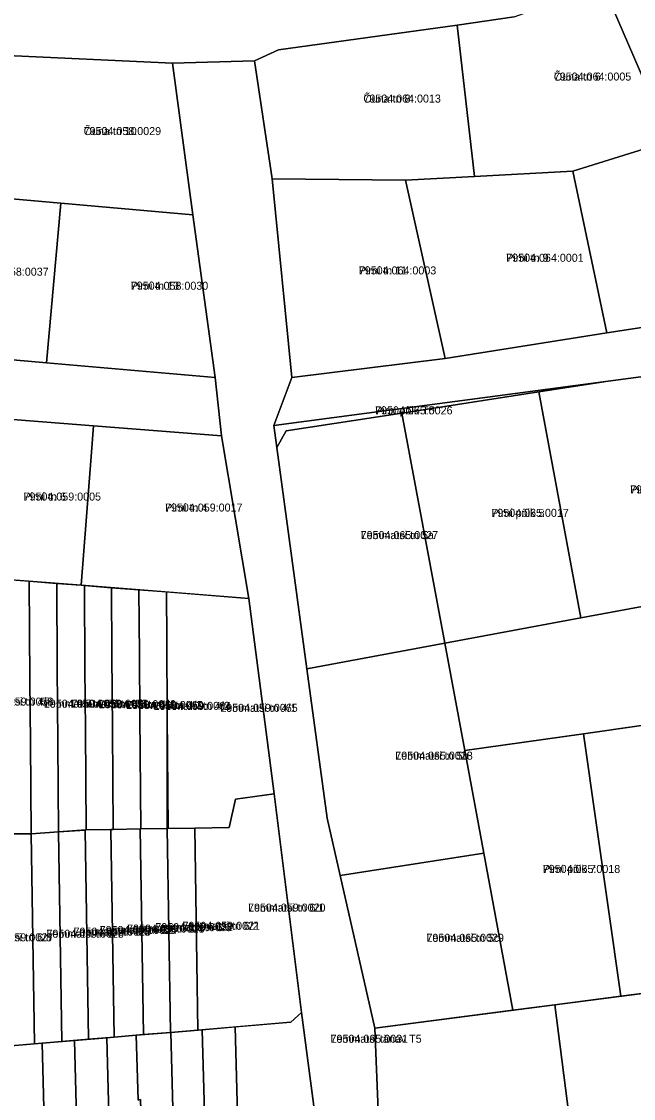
# Model space of a CAD drawing. Extents: x 643847 to 663718, y 6468443 to 6482775.
# Drawn here: x 657992.5 to 658107, y 6471569.9 to 6471771.7 of the extents above; entities that cross this region are included whole.
import ezdxf

# ---------------------------------------------------------------- set-up
doc = ezdxf.new("R2010")
doc.units = 0
for name, color, linetype in [('L_AADRESS', 7, 'Continuous'), ('PIIR', 7, 'Continuous'), ('TUNNUS', 7, 'Continuous')]:
    doc.layers.add(name, color=color, linetype=linetype)

msp = doc.modelspace()

# ---------------------------------------------------------------- linework, layer by layer
at = {"layer": 'PIIR'}
for points in [[(658130.86, 6471790.16), (658143.53, 6471759.24), (658139.36, 6471757.85), (658118.69, 6471750.96), (658113.89, 6471749.36), (658101.3, 6471778.58)], [(658084.71, 6471772.59), (658101.3, 6471778.58), (658113.89, 6471749.36), (658095.69, 6471743.62), (658077.27, 6471742.66), (658074.05, 6471771.01)], [(658040.59, 6471766.41), (658074.05, 6471771.01), (658077.27, 6471742.66), (658064.37, 6471741.98), (658039.4, 6471742.24), (658036.05, 6471764.29)], [(658020.75, 6471763.87), (658024.55, 6471735.47), (657999.78, 6471737.65), (657983.51, 6471739.07), (657988.38, 6471765.35)], [(658102.07, 6471713.38), (658095.69, 6471743.62), (658113.89, 6471749.36), (658118.69, 6471750.96), (658128.58, 6471717.44)], [(658240.59, 6471748.79), (658243.87, 6471740.33), (658192.37, 6471722.19), (658170.1, 6471714.25), (658165.76, 6471712.72), (658143.94, 6471709.85), (658115.89, 6471706.11), (658102.29, 6471704.3), (658039.68, 6471696.01), (658043.07, 6471704.97), (658071.81, 6471708.56), (658102.07, 6471713.38), (658128.58, 6471717.44), (658152.4, 6471721.29), (658165.18, 6471723.35), (658173.83, 6471725.83), (658194.24, 6471732.34)], [(658071.81, 6471708.56), (658064.37, 6471741.98), (658077.27, 6471742.66), (658095.69, 6471743.62), (658102.07, 6471713.38)], [(658043.07, 6471704.97), (658039.4, 6471742.24), (658064.37, 6471741.98), (658071.81, 6471708.56)], [(657966.25, 6471710.48), (657968.91, 6471740.35), (657983.51, 6471739.07), (657999.78, 6471737.65), (657997.15, 6471707.76)], [(658028.68, 6471704.99), (657997.15, 6471707.76), (657999.78, 6471737.65), (658024.55, 6471735.47)], [(658028.68, 6471704.99), (658029.88, 6471694.09), (658005.95, 6471695.96), (657982.03, 6471697.81), (657958.1, 6471699.66), (657934.19, 6471701.58), (657908.89, 6471703.62), (657886.93, 6471704.97), (657856.07, 6471706.87), (657856.98, 6471720.08), (657909.44, 6471715.48), (657934.36, 6471713.29), (657966.25, 6471710.48), (657997.15, 6471707.76)], [(658115.89, 6471706.11), (658123.55, 6471664.85), (658097.18, 6471659.96), (658089.32, 6471702.3), (658102.29, 6471704.3)], [(658102.29, 6471704.3), (658089.32, 6471702.3), (658063.69, 6471698.33), (658042.02, 6471694.97), (658040.24, 6471691.85), (658039.68, 6471696.01)], [(658089.32, 6471702.3), (658097.18, 6471659.96), (658071.69, 6471655.22), (658063.69, 6471698.33)], [(658005.95, 6471695.96), (658005.56, 6471690.97), (658003.62, 6471666.05), (657979.71, 6471667.91), (657981.64, 6471692.83), (657982.03, 6471697.81)], [(658063.69, 6471698.33), (658071.69, 6471655.22), (658045.88, 6471650.42), (658040.24, 6471691.85), (658042.02, 6471694.97)], [(658029.88, 6471694.09), (658035.03, 6471663.61), (658003.62, 6471666.05), (658005.56, 6471690.97), (658005.95, 6471695.96)], [(657993.88, 6471666.81), (657994.02, 6471648.2), (657994.1, 6471636.63), (657994.24, 6471619.48), (657989.23, 6471619.48), (657977.44, 6471619.45), (657975.43, 6471651.95), (657973.59, 6471652.12), (657975.1, 6471668.27), (657979.71, 6471667.91), (657988.87, 6471667.19)], [(657993.88, 6471666.81), (657999.03, 6471666.41), (657999.15, 6471650.58), (657999.26, 6471636.63), (657999.38, 6471619.88), (657994.24, 6471619.48), (657994.1, 6471636.63), (657994.02, 6471648.2)], [(657999.03, 6471666.41), (658003.62, 6471666.05), (658004.21, 6471666), (658004.33, 6471650.51), (658004.41, 6471639.05), (658004.55, 6471620.22), (657999.38, 6471619.88), (657999.26, 6471636.63), (657999.15, 6471650.58)], [(658004.21, 6471666), (658009.28, 6471665.61), (658009.37, 6471653.06), (658009.49, 6471639.06), (658009.62, 6471620.32), (658009.19, 6471620.31), (658004.55, 6471620.22), (658004.41, 6471639.05), (658004.33, 6471650.51)], [(658009.28, 6471665.61), (658014.44, 6471665.21), (658014.53, 6471653.09), (658014.62, 6471641.57), (658014.77, 6471620.41), (658014.65, 6471620.4), (658009.62, 6471620.32), (658009.49, 6471639.06), (658009.37, 6471653.06)], [(658019.57, 6471664.81), (658019.63, 6471655.68), (658019.74, 6471641.64), (658019.91, 6471620.49), (658019.72, 6471620.49), (658014.77, 6471620.41), (658014.62, 6471641.57), (658014.53, 6471653.09), (658014.44, 6471665.21)], [(658035.03, 6471663.61), (658039.75, 6471626.99), (658032.54, 6471626.01), (658031.36, 6471620.7), (658024.88, 6471620.58), (658019.72, 6471620.49), (658019.74, 6471641.64), (658019.63, 6471655.68), (658019.57, 6471664.81)], [(658071.69, 6471655.22), (658075.44, 6471635.08), (658079, 6471615.86), (658052.09, 6471611.67), (658049.69, 6471622.45), (658045.88, 6471650.42)], [(658119.87, 6471641.41), (658126.07, 6471591.82), (658104.69, 6471589.05), (658097.7, 6471638.25)], [(658097.7, 6471638.25), (658104.69, 6471589.05), (658092.3, 6471587.44), (658084.47, 6471586.43), (658079, 6471615.86), (658075.44, 6471635.08)], [(658031.36, 6471620.7), (658032.54, 6471626.01), (658039.75, 6471626.99), (658044.85, 6471585.99), (658042.89, 6471584.19), (658025.47, 6471582.73), (658024.88, 6471620.58)], [(658019.72, 6471620.49), (658020.34, 6471582.3), (658015.26, 6471581.87), (658014.65, 6471620.4), (658014.77, 6471620.41)], [(658024.88, 6471620.58), (658025.47, 6471582.73), (658020.34, 6471582.3), (658019.72, 6471620.49)], [(657977.44, 6471619.45), (657994.24, 6471619.48), (657994.85, 6471580.16), (657983, 6471579.16), (657980.44, 6471581.49), (657973.64, 6471595.24), (657972.88, 6471619.22)], [(657999.38, 6471619.88), (657999.99, 6471580.59), (657994.85, 6471580.16), (657994.24, 6471619.48)], [(658004.37, 6471620.21), (658004.99, 6471581), (657999.99, 6471580.59), (657999.38, 6471619.88)], [(658009.19, 6471620.31), (658009.82, 6471581.42), (658004.99, 6471581), (658004.37, 6471620.21), (658004.55, 6471620.22)], [(658014.65, 6471620.4), (658015.26, 6471581.87), (658009.82, 6471581.42), (658009.19, 6471620.31), (658009.62, 6471620.32)], [(658079, 6471615.86), (658084.47, 6471586.43), (658058.59, 6471583.07), (658052.09, 6471611.67)], [(658096.63, 6471553.82), (658092.3, 6471587.44), (658126.07, 6471591.82), (658130.25, 6471558.12)], [(658060, 6471549.15), (658058.59, 6471583.07), (658092.3, 6471587.44), (658096.63, 6471553.82)], [(658049.93, 6471547.63), (658033.46, 6471545.74), (658032.45, 6471583.31), (658042.89, 6471584.19), (658044.85, 6471585.99)], [(658021.43, 6471544.36), (658015.79, 6471543.72), (658015.23, 6471563.86), (658014.89, 6471563.86), (658014.74, 6471569.7), (658014.31, 6471569.62), (658013.93, 6471581.76), (658020.41, 6471582.3)], [(658027.32, 6471545.04), (658021.43, 6471544.36), (658020.41, 6471582.3), (658026.3, 6471582.8)], [(658033.46, 6471545.74), (658027.32, 6471545.04), (658026.3, 6471582.8), (658032.45, 6471583.31)], [(657997.29, 6471541.6), (657991.02, 6471540.88), (657983, 6471579.16), (657996.33, 6471580.28)], [(658003.34, 6471542.29), (657997.29, 6471541.6), (657996.33, 6471580.28), (658002.38, 6471580.79)], [(658009.39, 6471542.98), (658003.34, 6471542.29), (658002.38, 6471580.79), (658008.44, 6471581.3)], [(658014.31, 6471569.62), (658014.74, 6471569.7), (658014.89, 6471563.86), (658015.23, 6471563.86), (658015.79, 6471543.72), (658009.39, 6471542.98), (658008.44, 6471581.3), (658013.93, 6471581.76)]]:
    msp.add_lwpolyline(points, close=True, dxfattribs=at)
for points in [[(658084.71, 6471772.59), (658074.05, 6471771.01), (658040.59, 6471766.41), (658036.05, 6471764.29), (658020.75, 6471763.87), (657988.38, 6471765.35), (657966.11, 6471776.41)], [(658049.93, 6471547.63), (658044.85, 6471585.99), (658039.75, 6471626.99), (658035.03, 6471663.61), (658029.88, 6471694.09), (658028.68, 6471704.99), (658024.55, 6471735.47), (658020.75, 6471763.87), (658036.05, 6471764.29), (658039.4, 6471742.24), (658043.07, 6471704.97), (658039.68, 6471696.01), (658040.24, 6471691.85), (658045.88, 6471650.42), (658049.69, 6471622.45), (658052.09, 6471611.67), (658058.59, 6471583.07), (658060, 6471549.15)], [(658119.87, 6471641.41), (658097.7, 6471638.25), (658075.44, 6471635.08), (658071.69, 6471655.22), (658097.18, 6471659.96), (658123.55, 6471664.85)]]:
    msp.add_lwpolyline(points, dxfattribs=at)

# ---------------------------------------------------------------- texts
at = {"layer": 'L_AADRESS'}
for s, p in [('Õuna tn 6', (658092.13, 6471760.62)), ('Õuna tn 8', (658056.47, 6471756.5)), ('Õuna tn 10', (658004.08, 6471750.41)), ('Pirni tn 9', (658083.22, 6471726.67)), ('Pirni tn 11', (658055.61, 6471724.3)), ('Pirni tn 13', (658012.91, 6471721.43)), ('Pirni põik T5', (658058.66, 6471698.08)), ('Pirni tn 6', (657992.83, 6471681.93)), ('Pirni põik 3', (658106.43, 6471683.26)), ('Pirni tn 4', (658019.32, 6471679.87)), ('Pirni põik 5', (658080.43, 6471678.88)), ('Lemmatsi tn 5a', (658055.96, 6471674.71)), ('Lemmatsi tn 4/7', (657983.92, 6471643.52)), ('Lemmatsi tn 4/6', (657996.63, 6471643.13)), ('Lemmatsi tn 4/5', (658001.79, 6471643.12)), ('Lemmatsi tn 4/4', (658006.91, 6471643.03)), ('Lemmatsi tn 4/3', (658012.03, 6471642.88)), ('Lemmatsi tn 4/2', (658017.17, 6471642.72)), ('Lemmatsi tn 4/1', (658029.66, 6471642.35)), ('Lemmatsi tn 5b', (658062.44, 6471633.39)), ('Pirni põik 7', (658090.06, 6471612.16)), ('Lemmatsi tn 6/1', (658034.87, 6471604.92)), ('Lemmatsi tn 6/5', (658007.09, 6471600.73)), ('Lemmatsi tn 6/4', (658012.22, 6471600.99)), ('Lemmatsi tn 6/3', (658017.5, 6471601.26)), ('Lemmatsi tn 6/2', (658022.59, 6471601.51)), ('Lemmatsi tn 6/8', (657983.87, 6471599.35)), ('Lemmatsi tn 6/7', (657997.12, 6471600.03)), ('Lemmatsi tn 6/6', (658002.19, 6471600.42)), ('Lemmatsi tn 5c', (658068.28, 6471599.26)), ('Lemmatsi tänav T5', (658050.32, 6471580.35))]:
    msp.add_text(s, height=1.5, dxfattribs=at).set_placement(p)
at = {"layer": 'TUNNUS'}
for s, p in [('79504:064:0005', (658092.13, 6471760.62)), ('79504:064:0013', (658056.47, 6471756.5)), ('79504:058:0029', (658004.08, 6471750.41)), ('79504:064:0001', (658083.22, 6471726.67)), ('79504:058:0037', (657983.02, 6471724.06)), ('79504:064:0003', (658055.61, 6471724.3)), ('79504:058:0030', (658012.91, 6471721.43)), ('79504:065:0026', (658058.66, 6471698.08)), ('79504:059:0005', (657992.83, 6471681.93)), ('79504:065:0016', (658106.43, 6471683.26)), ('79504:059:0017', (658019.32, 6471679.87)), ('79504:065:0017', (658080.43, 6471678.88)), ('79504:065:0027', (658055.96, 6471674.71)), ('79504:059:0058', (657983.92, 6471643.52)), ('79504:059:0052', (657996.63, 6471643.13)), ('79504:059:0051', (658001.79, 6471643.12)), ('79504:059:0049', (658006.91, 6471643.03)), ('79504:059:0060', (658012.03, 6471642.88)), ('79504:059:0064', (658017.17, 6471642.72)), ('79504:059:0065', (658029.66, 6471642.35)), ('79504:065:0028', (658062.44, 6471633.39)), ('79504:065:0018', (658090.06, 6471612.16)), ('79504:059:0020', (658034.87, 6471604.92)), ('79504:059:0023', (658012.22, 6471600.99)), ('79504:059:0022', (658017.5, 6471601.26)), ('79504:059:0021', (658022.59, 6471601.51)), ('79504:059:0027', (657983.87, 6471599.35)), ('79504:059:0026', (657997.12, 6471600.03)), ('79504:059:0025', (658002.19, 6471600.42)), ('79504:059:0024', (658007.09, 6471600.73)), ('79504:065:0029', (658068.28, 6471599.26)), ('79504:065:0031', (658050.32, 6471580.35))]:
    msp.add_text(s, height=1.5, dxfattribs=at).set_placement(p)

doc.saveas('drawing.dxf')
